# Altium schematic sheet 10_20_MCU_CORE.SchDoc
size 289 x 397 mm
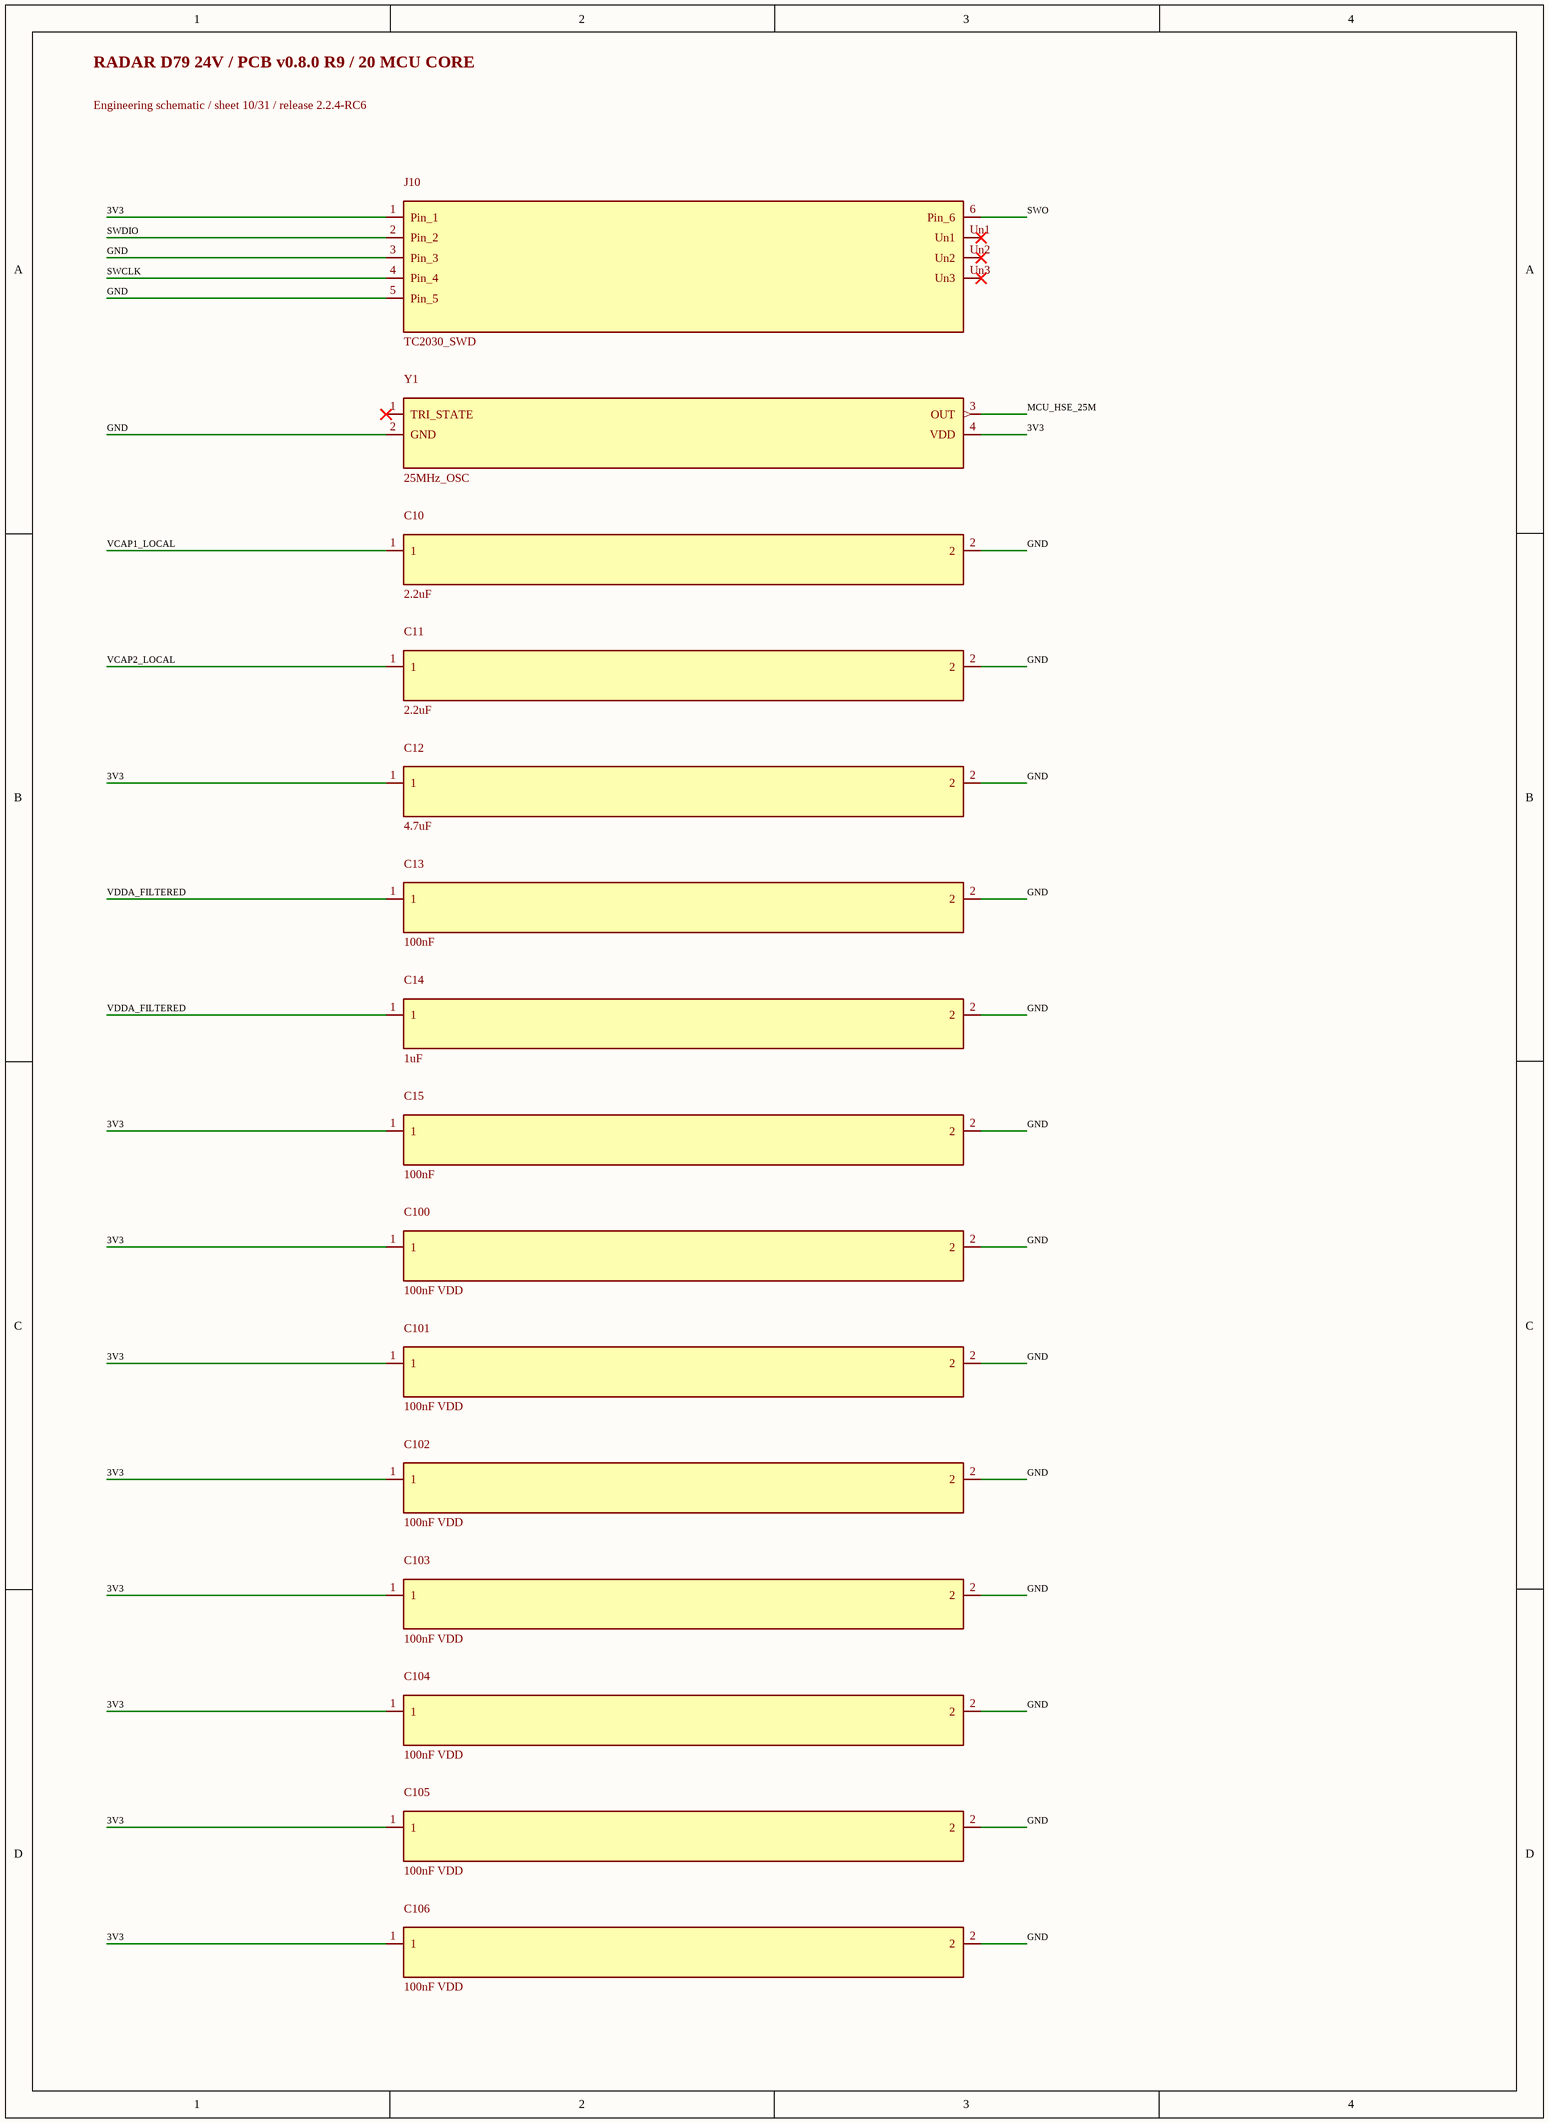
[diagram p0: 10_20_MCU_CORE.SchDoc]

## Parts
C10  2.2uF  [C_0603_1608Metric]
C11  2.2uF  [C_0603_1608Metric]
C12  4.7uF  [C_0805_2012Metric]
C13  100nF  [C_0402_1005Metric]
C14  1uF  [C_0603_1608Metric]
C15  100nF  [C_0402_1005Metric]
C100  100nF VDD  [C_0402_1005Metric]
C101  100nF VDD  [C_0402_1005Metric]
C102  100nF VDD  [C_0402_1005Metric]
C103  100nF VDD  [C_0402_1005Metric]
C104  100nF VDD  [C_0402_1005Metric]
C105  100nF VDD  [C_0402_1005Metric]
C106  100nF VDD  [C_0402_1005Metric]
J10  TC2030_SWD  [TagConnect_TC2030_NL]
Y1  25MHz_OSC  [Oscillator_SMD_ECS_2520MV-xxx-xx-4Pin_2.5x2.0mm]

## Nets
3V3: C12.1 C15.1 C100.1 C101.1 C102.1 C103.1 C104.1 C105.1 C106.1 J10.1(Pin_1) Y1.4(VDD)
GND: C10.2 C11.2 C12.2 C13.2 C14.2 C15.2 C100.2 C101.2 C102.2 C103.2 C104.2 C105.2 C106.2 J10.3(Pin_3) J10.5(Pin_5) Y1.2(GND)
MCU_HSE_25M: Y1.3(OUT)
SWCLK: J10.4(Pin_4)
SWDIO: J10.2(Pin_2)
SWO: J10.6(Pin_6)
VCAP1_LOCAL: C10.1
VCAP2_LOCAL: C11.1
VDDA_FILTERED: C13.1 C14.1

Not connected (* = marked no-connect by the designer): J10 Un1* Un2* Un3*; Y1 1(TRI_STATE)*

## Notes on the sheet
- RADAR D79 24V / PCB v0.8.0 R9 / 20 MCU CORE
- Engineering schematic / sheet 10/31 / release 2.2.4-RC6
